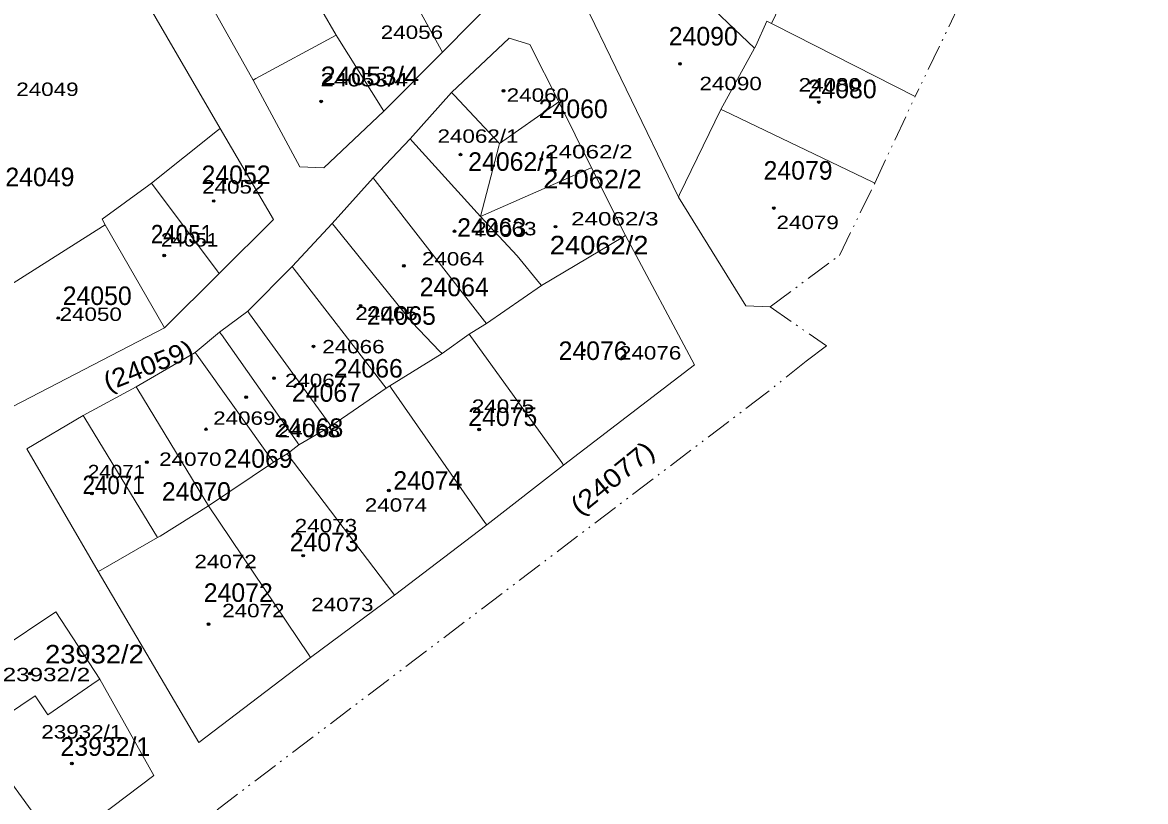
# Model space of a CAD drawing. Extents: x 649608 to 651081, y 237980 to 241202.
# Drawn here: x 650826.5 to 651044.4, y 238207.6 to 238358.7 of the extents above; entities that cross this region are included whole.
import ezdxf

# ---------------------------------------------------------------- set-up
doc = ezdxf.new("R2010")
doc.units = 0
doc.header["$PDMODE"] = 32
doc.header["$PDSIZE"] = 0.5
doc.linetypes.add('DASH_DOUBLE_DOT', pattern=[9.2, 5, -1.2, 0.3, -1.2, 0.3, -1.2])
for name, color, linetype in [('19', 7, 'Continuous'), ('20', 7, 'Continuous'), ('6', 7, 'Continuous')]:
    doc.layers.add(name, color=color, linetype=linetype)
for name, color, linetype, lineweight in [('2', 7, 'DASH_DOUBLE_DOT', 13), ('3', 7, 'Continuous', 13), ('5', 7, 'Continuous', 13), ('52', 7, 'DASH_DOUBLE_DOT', 13)]:
    doc.layers.add(name, color=color, linetype=linetype, lineweight=lineweight)

msp = doc.modelspace()

# ---------------------------------------------------------------- linework, layer by layer
at = {"layer": '2'}
for points in [[(651044.396, 238429.284), (651027.852, 238400.968), (651018.368, 238381.839), (651008.402, 238362.401), (650999.718, 238344.376)], [(650971.563, 238303.584), (650985.006, 238313.517), (650991.86, 238327.571), (650999.718, 238344.376)]]:
    msp.add_lwpolyline(points, dxfattribs=at)
at = {"layer": '3'}
msp.add_line((650833.028, 238244.372), (650810.115, 238229.097), dxfattribs=at)
for points in [[(650896.629, 238341.525), (650885.025, 238330.555), (650880.347, 238330.711), (650871.33, 238347.558), (650863.025, 238362.258), (650853.548, 238378.601), (650845.597, 238391.685), (650835.988, 238405.983), (650826.605, 238419.813)], [(650831.543, 238395.385), (650833.862, 238391.545), (650864.894, 238338.148)], [(650944.611, 238376.541), (650933.47, 238366.808), (650953.787, 238324.857)], [(650919.66, 238364.802), (650908.054, 238352.949), (650896.629, 238341.525)], [(650854.104, 238299.459), (650822.931, 238283.334), (650813.072, 238300.813), (650775.665, 238361.941)], [(650930.61, 238343.334), (650924.957, 238354.472), (650920.975, 238355.704), (650909.792, 238345.112), (650901.731, 238336.143), (650894.583, 238328.576), (650886.639, 238319.749), (650878.896, 238311.361), (650870.245, 238302.695), (650864.798, 238298.671), (650860.06, 238294.687), (650848.609, 238288.055), (650838.346, 238282.461)], [(650931.516, 238272.851), (650956.891, 238292.34), (650943.519, 238317.37), (650936.899, 238330.529), (650930.61, 238343.334)], [(650864.894, 238338.148), (650875.213, 238320.492), (650864.709, 238310.052), (650854.104, 238299.459)], [(650953.787, 238324.857), (650966.86, 238303.765), (650971.563, 238303.584)], [(650838.346, 238282.461), (650827.365, 238276.034), (650841.225, 238252.215), (650860.767, 238219.05)], [(650860.767, 238219.05), (650882.404, 238235.563), (650898.74, 238247.614), (650916.613, 238261.253), (650931.516, 238272.851)], [(650833.498, 238198.629), (650852.011, 238212.621), (650841.55, 238231.355), (650833.028, 238244.372)]]:
    msp.add_lwpolyline(points, dxfattribs=at)
at = {"layer": '5'}
for points in [[(650891.47, 238382.627), (650891.65, 238382.678), (650907.778, 238353.449), (650908.054, 238352.949)], [(650944.611, 238376.541), (650945.111, 238376.065), (650968.571, 238353.722), (650962.028, 238341.864)], [(650878.792, 238371.179), (650879.082, 238370.679), (650887.429, 238356.276)], [(650968.571, 238353.722), (650968.793, 238354.222), (650970.908, 238358.996), (650971.828, 238358.515), (650974.241, 238363.562)], [(650971.828, 238358.515), (650972.328, 238358.262), (650999.718, 238344.376)], [(650887.429, 238356.276), (650871.83, 238347.829), (650871.33, 238347.558)], [(650887.429, 238356.276), (650887.741, 238355.776), (650896.317, 238342.025), (650896.629, 238341.525)], [(650909.792, 238345.112), (650910.263, 238344.612), (650919.114, 238335.216)], [(650919.114, 238335.216), (650930.11, 238342.981), (650930.61, 238343.334)], [(650962.028, 238341.864), (650954.029, 238325.357), (650953.787, 238324.857)], [(650962.028, 238341.864), (650962.528, 238341.624), (650991.36, 238327.811), (650991.86, 238327.571)], [(650864.894, 238338.148), (650864.394, 238337.75), (650851.578, 238327.559)], [(650915.424, 238321.08), (650902.186, 238335.643), (650901.731, 238336.143)], [(650919.114, 238335.216), (650918.983, 238334.716), (650915.424, 238321.08)], [(650915.424, 238321.08), (650936.399, 238330.309), (650936.899, 238330.529)], [(650851.578, 238327.559), (650851.078, 238327.193), (650842.002, 238320.55), (650842.562, 238319.464), (650854.104, 238299.459)], [(650851.578, 238327.559), (650864.334, 238310.552), (650864.709, 238310.052)], [(650894.583, 238328.576), (650894.971, 238328.076), (650916.15, 238300.806), (650916.538, 238300.306)], [(650927.255, 238307.687), (650926.844, 238308.187), (650922.528, 238313.437), (650915.424, 238321.08)], [(650842.562, 238319.464), (650842.062, 238319.148), (650813.572, 238301.129), (650813.072, 238300.813)], [(650907.936, 238294.483), (650907.456, 238294.983), (650902.119, 238300.548), (650887.042, 238319.249), (650886.639, 238319.749)], [(650927.255, 238307.687), (650943.019, 238317.072), (650943.519, 238317.37)], [(650897.108, 238287.804), (650879.283, 238310.861), (650878.896, 238311.361)], [(650913.21, 238298.265), (650913.71, 238298.572), (650916.538, 238300.306), (650927.255, 238307.687)], [(650870.245, 238302.695), (650870.607, 238302.195), (650886.019, 238280.919), (650886.381, 238280.419)], [(650880.161, 238276.79), (650879.81, 238277.29), (650865.149, 238298.171), (650864.798, 238298.671)], [(650931.516, 238272.851), (650931.156, 238273.351), (650913.21, 238298.265), (650907.936, 238294.483), (650897.801, 238288.231), (650897.108, 238287.804)], [(650860.06, 238294.687), (650860.418, 238294.187), (650875.271, 238273.437), (650862.624, 238264.942)], [(650862.624, 238264.942), (650848.912, 238287.555), (650848.609, 238288.055)], [(650897.108, 238287.804), (650886.381, 238280.419), (650880.161, 238276.79)], [(650916.613, 238261.253), (650916.264, 238261.753), (650898.15, 238287.731), (650897.801, 238288.231)], [(650852.743, 238258.792), (650838.65, 238281.961), (650838.346, 238282.461)], [(650880.161, 238276.79), (650878.382, 238275.412), (650877.882, 238275.025)], [(650877.882, 238275.025), (650875.771, 238273.741), (650875.271, 238273.437)], [(650898.74, 238247.614), (650898.36, 238248.114), (650877.882, 238275.025)], [(650852.743, 238258.792), (650853.243, 238259.103), (650862.624, 238264.942)], [(650882.404, 238235.563), (650882.067, 238236.063), (650862.624, 238264.942)], [(650841.225, 238252.215), (650841.725, 238252.501), (650852.743, 238258.792)], [(650817.634, 238220.462), (650829.028, 238228.095), (650831.481, 238224.416), (650841.05, 238231.01), (650841.55, 238231.355)], [(650833.498, 238198.629), (650833.135, 238199.129), (650817.634, 238220.462)]]:
    msp.add_lwpolyline(points, dxfattribs=at)
at = {"layer": '52'}
msp.add_lwpolyline([(650971.563, 238303.584), (650982.492, 238295.992), (650978.586, 238293.02), (650970.875, 238286.874), (650811.903, 238166.241), (650803.737, 238160.273), (650800.084, 238157.225)], dxfattribs=at)
at = {"layer": '6'}
for p in [(650954.087, 238350.699), (650919.845, 238345.46), (650884.499, 238343.415), (650981.009, 238343.283), (650911.531, 238333.096), (650927.202, 238332.207), (650863.638, 238324.1), (650972.303, 238322.724), (650910.351, 238318.224), (650929.951, 238319.108), (650854.057, 238313.509), (650900.544, 238311.529), (650892.138, 238303.776), (650833.492, 238301.399), (650883.016, 238295.89), (650935.447, 238295.11), (650875.347, 238289.742), (650869.948, 238286.054), (650862.156, 238279.814), (650915.124, 238279.759), (650850.662, 238273.423), (650897.625, 238267.922), (650839.985, 238267.338), (650881.008, 238255.294), (650862.659, 238241.996), (650827.975, 238232.417), (650836.148, 238214.992)]:
    msp.add_point(p, dxfattribs=at)

# ---------------------------------------------------------------- texts
at = {"layer": '19'}
for s, p in [('24090', (650951.92, 238354.259)), ('24080', (650978.853, 238344.021)), ('24060', (650926.696, 238340.181)), ('24062/1', (650913.017, 238329.942)), ('24052', (650861.289, 238327.383)), ('24079', (650970.303, 238328.236)), ('24049', (650823.24, 238326.956)), ('24063', (650910.878, 238317.144)), ('24064', (650903.611, 238305.625)), ('24050', (650834.355, 238303.919)), ('24065', (650893.35, 238300.079)), ('24076', (650930.546, 238293.254)), ('24066', (650886.939, 238289.841)), ('24067', (650878.816, 238285.148)), ('24075', (650913.017, 238280.455)), ('24068', (650875.395, 238278.322)), ('24069', (650865.563, 238272.35)), ('24074', (650898.482, 238268.084)), ('24070', (650853.593, 238265.951)), ('24073', (650878.389, 238256.139)), ('24072', (650861.716, 238246.327)), ('23932/1', (650833.927, 238216.464))]:
    msp.add_text(s, height=3.6, dxfattribs=at).set_placement(p)
for s, width, p in [('24053/4', 1.1, (650884.374, 238346.58)), ('24062/2', 1.1, (650927.552, 238326.529)), ('24051', 0.9, (650851.456, 238315.864)), ('24062/2', 1.1, (650928.835, 238313.731)), ('24071', 0.9, (650838.203, 238267.23)), ('23932/2', 1.1, (650830.934, 238234.382))]:
    msp.add_text(s, height=3.6, dxfattribs=dict(at, width=width)).set_placement(p)
for s, rotation, width, p in [('(24059)', 21.755, 1.1, (650843.146, 238287.141)), ('(24077)', 39.035, 1.15, (650934.691, 238262.956))]:
    msp.add_text(s, height=3.6, rotation=rotation, dxfattribs=dict(at, width=width)).set_placement(p)
at = {"layer": '20'}
for s, width, p in [('24056', 1.25, (650896.049, 238355.529)), ('24053/4', 1.35, (650884.358, 238346.319)), ('24049', 1.25, (650825.35, 238344.467)), ('24090', 1.25, (650957.872, 238345.581)), ('24080', 1.25, (650977.1, 238345.334)), ('24060', 1.25, (650920.478, 238343.349)), ('24062/1', 1.25, (650907.059, 238335.382)), ('24062/2', 1.35, (650927.944, 238332.357)), ('24052', 1.25, (650861.392, 238325.536)), ('24063', 1.25, (650914.173, 238317.432)), ('24062/3', 1.35, (650932.971, 238319.348)), ('24079', 1.25, (650972.812, 238318.648)), ('24051', 1.15, (650853.404, 238315.268)), ('24064', 1.25, (650904.041, 238311.583)), ('24050', 1.25, (650833.745, 238300.829)), ('24065', 1.25, (650891.117, 238300.994)), ('24066', 1.25, (650884.702, 238294.54)), ('24076', 1.25, (650942.257, 238293.339)), ('24067', 1.25, (650877.456, 238287.985)), ('24075', 1.25, (650913.719, 238282.986)), ('24069', 1.25, (650863.54, 238280.68)), ('24068', 1.25, (650876.055, 238278.25)), ('24070', 1.25, (650853.066, 238272.714)), ('24071', 1.15, (650839.232, 238270.31)), ('24074', 1.25, (650892.953, 238263.825)), ('24073', 1.25, (650879.366, 238259.822)), ('24072', 1.25, (650859.915, 238252.863)), ('24072', 1.25, (650865.293, 238243.344)), ('24073', 1.25, (650882.559, 238244.522)), ('23932/2', 1.35, (650822.712, 238230.938)), ('23932/1', 1.25, (650830.207, 238219.829))]:
    msp.add_text(s, height=2.6, dxfattribs=dict(at, width=width)).set_placement(p)

doc.saveas('drawing.dxf')
